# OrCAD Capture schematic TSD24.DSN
size A; title: TSDxx Unidirectional Protection Diodes in SOD-323; rev: 1.0; note: Datasheet: SLVSH43
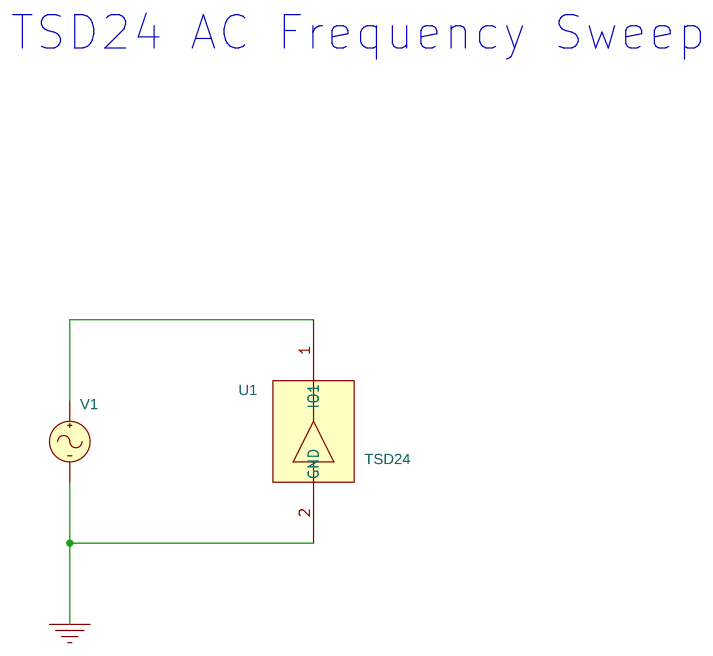
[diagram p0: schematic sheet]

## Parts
U1  TSD24
V1  VAC

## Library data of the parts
U1 = TSD24
V1 = VAC

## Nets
0: U1.2(GND) V1.2(-)
N02927: U1.1(IO1) V1.1(+)

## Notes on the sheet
- TSD24 AC Frequency Sweep
